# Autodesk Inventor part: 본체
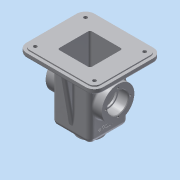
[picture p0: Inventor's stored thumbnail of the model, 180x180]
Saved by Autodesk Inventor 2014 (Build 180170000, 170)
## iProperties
Created: 2015-12
Part Number: 본체
Material: 알루미늄 6061
Document SubType Name: Modeling
Designer: Administrator
Density: 2.71 g/cm^3
Appearance: 알루미늄 - 평지
Mass: 854.215 g
Surface Area: 937.334 cm^2
Volume: 315.208 cm^3
Author: Administrator
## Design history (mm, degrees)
sketch "스케치1"
  geometry: L1 (32.5, 32.5)-(-32.5, 32.5); L2 (-32.5, 32.5)-(-32.5, -32.5); L3 (-32.5, -32.5)-(32.5, -32.5); L4 (32.5, -32.5)-(32.5, 32.5); L5 (32.5, 32.5)-(-32.5, -32.5); L6 (-32.5, 32.5)-(32.5, -32.5); 1 further point
  constraints: 12 end point, 2 midpoint, 2 parallel, 1 horizontal, 1 perpendicular
  dimensions: "d0" = 65 distance of L3.end L2.end; "d1" = 65 distance of L2.end L1.end
extrude "돌출1" new body sketch "스케치1" stored distance "d2" = 110; taper "d3" = 0 deg
sketch "스케치2"
  geometry: C1 r 20 at (0, 0); 1 further point
  constraints: 1 centre point, 1 coincident
  dimensions: "d4" = 40 diameter of C1
extrude "돌출2" join sketch "스케치2" distance "d5" = 10; taper "d6" = 0 deg
sketch "스케치5"
  geometry: C1 r 27.5 at (0, 0); 1 further point
  constraints: 1 centre point, 1 coincident
  dimensions: "d15" = 55 diameter of C1
extrude "돌출5" join sketch "스케치5" stored distance "d16" = 95; taper "d17" = 0 deg
sketch "스케치6"
  geometry: C1 r 27.5 at (0, 0) reference; C2 r 17.5 at (0, 0)
  constraints: 1 centre point, 1 coincident
  dimensions: "d18" = 35 diameter of C2
extrude "돌출6" cut sketch "스케치6" distance "d19" = 17; taper "d20" = 0 deg
sketch "스케치7"
  geometry: C1 r 27.5 at (0, 0) reference; C2 r 17.5 at (0, 0)
  constraints: 1 centre point, 1 coincident
  dimensions: "d21" = 35 diameter of C2
extrude "돌출7" cut sketch "스케치7" distance "d22" = 17; taper "d23" = 0 deg
sketch "스케치9"
  geometry: C1 r 20 at (0, 0) reference; C2 r 10.5 at (0, 0)
  constraints: 1 centre point, 1 coincident
  dimensions: "d28" = 21 diameter of C2
extrude "돌출9" cut sketch "스케치9" distance "d29" = 15; taper "d30" = 0 deg
sketch "스케치11"
  geometry: L1 (32.5, 32.5)-(-32.5, 32.5) reference; L2 (-32.5, 32.5)-(-32.5, -32.5) reference; L3 (-32.5, -32.5)-(32.5, -32.5) reference; L4 (32.5, -32.5)-(32.5, 32.5) reference; L5 (-60, -52.5)-(60, -52.5); L6 (60, -52.5)-(60, 52.5); L7 (60, 52.5)-(-60, 52.5); L8 (-60, 52.5)-(-60, -52.5); L9 (-60, -52.5)-(60, 52.5); L10 (60, -52.5)-(-60, 52.5); 1 further point
  constraints: 12 end point, 2 midpoint, 2 parallel, 1 horizontal, 1 perpendicular
  dimensions: "d31" = 120 distance of L7.end L6.end; "d32" = 105 distance of L6.end L5.end
extrude "돌출10" join sketch "스케치11" distance "d33" = 2; taper "d34" = 0 deg
sketch "스케치12"
  geometry: L1 (32.5, -32.5)-(32.5, 32.5) reference; L2 (-32.5, -32.5)-(32.5, -32.5) reference; L3 (-32.5, 32.5)-(-32.5, -32.5) reference; L4 (32.5, 32.5)-(-32.5, 32.5) reference; L5 (-65, -57.5)-(65, -57.5); L6 (65, -57.5)-(65, 57.5); L7 (65, 57.5)-(-65, 57.5); L8 (-65, 57.5)-(-65, -57.5); L9 (-65, -57.5)-(65, 57.5); L10 (65, -57.5)-(-65, 57.5); 1 further point
  constraints: 12 end point, 2 midpoint, 2 parallel, 1 horizontal, 1 perpendicular
  dimensions: "d35" = 130 distance of L7.end L6.end; "d36" = 115 distance of L6.end L5.end
extrude "돌출11" join sketch "스케치12" distance "d37" = 8; taper "d38" = 0 deg
sketch "스케치13"
  geometry: L1 (-27.5, -27.5)-(27.5, -27.5); L2 (27.5, -27.5)-(27.5, 27.5); L3 (27.5, 27.5)-(-27.5, 27.5); L4 (-27.5, 27.5)-(-27.5, -27.5); L5 (-27.5, -27.5)-(27.5, 27.5); L6 (27.5, -27.5)-(-27.5, 27.5); 1 further point
  constraints: 12 end point, 2 midpoint, 2 parallel, 1 horizontal, 1 perpendicular
  dimensions: "d39" = 55 distance of L3.end L2.end; "d40" = 55 distance of L2.end L1.end
extrude "돌출12" cut sketch "스케치13" distance "d41" = 105; taper "d42" = 0 deg
sketch "스케치14"
  geometry: L1 (-100, 90)-(-100, -25) reference; L2 (-108, 90)-(-108, -25) reference; L3 (-110, -20)-(-110, 85) reference; L4 (-100, 32.5)-(-100, 29.5); L5 (-100, 29.5)-(-82.336, 29.5); L6 (-100, 32.5)-(-100, 35.5); L7 (-100, 35.5)-(-82.336, 35.5); C1 r 27.5 at (-55, 32.5) reference; A1 r 27.5 centre (-55, 32.5) between (-82.336, 29.5) and (-82.336, 35.5) reference; A2 r 27.5 centre (-55, 32.5) between (-82.336, 35.5) and (-82.336, 29.5)
  constraints: 8 end point, 4 point on circle, 2 perpendicular, 2 point on line, 1 centre point, 1 coincident, 1 midpoint
  dimensions: "d43" = 3 distance of L4.start L4.end; "d44" = 3 distance of L4.start L6.end
extrude "돌출13" join sketch "스케치14" distance "d45" = 10; taper "d46" = 0 deg
sketch "스케치15"
  geometry: L1 (-57.5, 45)-(57.5, 45) reference; L2 (-32.5, -55)-(-32.5, 45) reference; L3 (32.5, -55)-(32.5, 45) reference; L4 (-57.5, 45)-(-47.5, 45); L5 (-47.5, 45)-(-32.5, -40.069); L6 (-32.5, -40.069)-(-32.5, 45); 1 further point
  constraints: 6 end point, 2 point on line, 1 collinear
  dimensions: "d47" = 10 distance of L1.start L4.end; "d48" = 100 deg angle of L4 L5
extrude "돌출14" join sketch "스케치15" stored distance "d49" = 10; taper "d50" = 0 deg
sketch "스케치16"
  geometry: L1 (-50, -42.5)-(50, -42.5); L2 (50, -42.5)-(50, 42.5); L3 (50, 42.5)-(-50, 42.5); L4 (-50, 42.5)-(-50, -42.5); L5 (-50, -42.5)-(50, 42.5); L6 (50, -42.5)-(-50, 42.5); C1 r 7.5 at (-50, 42.5); C2 r 7.5 at (50, 42.5); C3 r 7.5 at (50, -42.5); C4 r 7.5 at (-50, -42.5); 1 further point
  constraints: 12 end point, 4 centre point, 4 coincident, 2 midpoint, 2 parallel, 1 horizontal, 1 perpendicular
  dimensions: "d51" = 100 distance of L3.end L2.end; "d52" = 85 distance of L2.end L1.end; "d53" = 15 diameter of C1; "d54" = 15 diameter of C2; "d55" = 15 diameter of C3; "d56" = 15 diameter of C4
extrude "돌출15" join sketch "스케치16" distance "d57" = 3; taper "d58" = 0 deg
sketch "스케치17"
  geometry: C1 r 7.5 at (0, 0) reference; C2 r 3 at (0, 0); 1 further point
  constraints: 1 centre point, 1 coincident
  dimensions: "d59" = 6 diameter of C2
extrude "돌출16" cut sketch "스케치17" distance "d60" = 13; taper "d61" = 0 deg
sketch "스케치18"
  geometry: C1 r 7.5 at (0, 0) reference; C2 r 3 at (0, 0); 1 further point
  constraints: 1 centre point, 1 coincident
  dimensions: "d62" = 6 diameter of C2
extrude "돌출17" cut sketch "스케치18" distance "d63" = 13; taper "d64" = 0 deg
sketch "스케치19"
  geometry: C1 r 7.5 at (0, 0) reference; C2 r 3 at (0, 0); 1 further point
  constraints: 1 centre point, 1 coincident
  dimensions: "d65" = 6 diameter of C2
extrude "돌출18" cut sketch "스케치19" distance "d66" = 13; taper "d67" = 0 deg
sketch "스케치20"
  geometry: C1 r 7.5 at (0, 0) reference; C2 r 3 at (0, 0); 1 further point
  constraints: 1 centre point, 1 coincident
  dimensions: "d68" = 6 diameter of C2
extrude "돌출19" cut sketch "스케치20" distance "d69" = 13; taper "d70" = 0 deg
sketch "스케치21"
  geometry: C1 r 17.5 at (0, 0) reference; C2 r 15 at (0, 0)
  constraints: 1 centre point, 1 coincident
  dimensions: "d71" = 30 diameter of C2
extrude "돌출20" cut sketch "스케치21" distance "d72" = 100; taper "d73" = 0 deg
sketch "스케치22" dims "d74" = 42
  geometry: C1 r 27.5 at (0, 0) reference; 2 further points
  constraints: 1 coincident, 1 horizontal alignment, 2 other
hole "구멍1" sketch "스케치22" at (-21, 0) diameter "d75" = 3.242; stored, may be unused: countersink angle "d79" = 90 deg, drill point angle "d81" = 118 deg; dims "d76" = 8, "d77" = 4, "d78" = 2, "d80" = 10
sketch "스케치23" dims "d85" = 29
  geometry: C1 r 20 at (0, 0) reference; 2 further points
  constraints: 1 coincident, 1 vertical alignment, 2 other
hole "구멍2" sketch "스케치23" at (0, 14.5) diameter "d86" = 2.459; stored, may be unused: countersink angle "d90" = 90 deg, drill point angle "d92" = 118 deg; dims "d87" = 7, "d88" = 4, "d89" = 2, "d91" = 9
sketch "스케치24"
  geometry: L1 (0, 65)-(0, 0) reference; L2 (0, 65)-(0, 32.5); L3 (10, 12.5)-(10, 52.5) reference; L4 (10, 32.5)-(-16, 32.5); 1 further point
  constraints: 4 end point, 2 midpoint, 1 coincident, 1 perpendicular, 1 other
  dimensions: "d96" = 32.5 distance of L1.start L2.end; "d97" = 26 distance of L4.start L4.end
feature "엠보싱1" sketch "스케치24" dims "d98" = 0.5, "d99" = 0
fillet "모깎기1" dims "d100" = 3
fillet "모깎기2" dims "d101" = 15
fillet "모깎기3" dims "d102" = 8
fillet "모깎기4" dims "d103" = 3
fillet "모깎기5" dims "d104" = 8
fillet "모깎기6" dims "d105" = 3
fillet "모깎기7" dims "d106" = 3
fillet "모깎기8" dims "d107" = 10
fillet "모깎기9" dims "d108" = 3
chamfer "모따기1" distance "d109" = 1; stored, may be unused: second distance "d110" = 2, angle "d111" = 45 deg
fillet "모깎기10" dims "d112" = 0.3
node "솔리드1"
mirror "대칭1"
mirror "대칭2"
pattern_circular "원형 패턴1" dims angle "d83" = 360 deg
mirror "대칭3"
pattern_circular "원형 패턴2" dims angle "d94" = 360 deg
